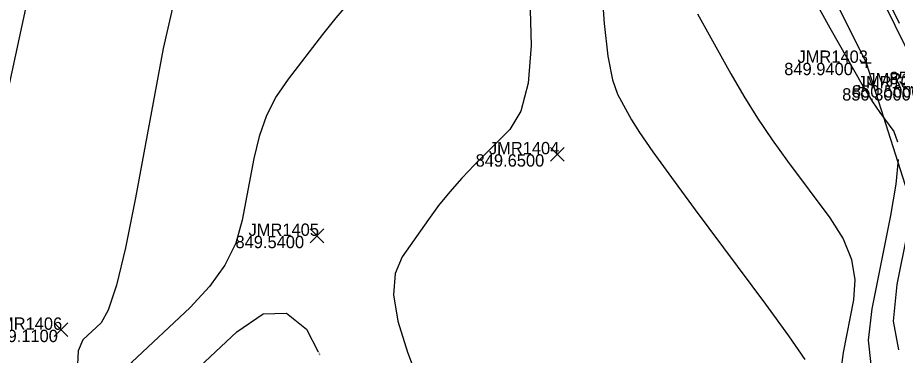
# Model space of a CAD drawing. Extents: x 1654928 to 1810050, y 486881 to 626330.
# Drawn here: x 1801294.2 to 1801380, y 489843.7 to 489876.6 of the extents above; entities that cross this region are included whole.
import ezdxf

# ---------------------------------------------------------------- set-up
doc = ezdxf.new("R2010")
doc.units = 0
for name, color, linetype in [('DT_X_Contour_Major', 7, 'Continuous'), ('DT_X_Contour_Minor', 7, 'Continuous'), ('RD_X_Fence', 7, 'Continuous'), ('SV_X_Occupation_Line', 7, 'Continuous'), ('SV_X_Random_Point', 7, 'Continuous'), ('SV_X_Shot_Marker', 7, 'Continuous'), ('SV_X_Text_Elevation', 7, 'Continuous'), ('SV_X_Text_Name', 7, 'Continuous')]:
    doc.layers.add(name, color=color, linetype=linetype)

msp = doc.modelspace()

# ---------------------------------------------------------------- linework, layer by layer
at = {"layer": 'DT_X_Contour_Major'}
for points in [[(1801292.361, 489865.603), (1801296.572, 489884.906)], [(1801360.479, 489876.984), (1801363.724, 489871.142), (1801364.981, 489868.967), (1801366.321, 489866.823), (1801367.743, 489864.709), (1801369.247, 489862.626), (1801373.367, 489857.111), (1801374.671, 489855.061), (1801375.493, 489853.047), (1801375.833, 489851.068), (1801375.691, 489849.125), (1801374.67, 489843.993), (1801374.464, 489842.265)]]:
    msp.add_lwpolyline(points, dxfattribs=at)
at = {"layer": 'DT_X_Contour_Minor'}
for points in [[(1801373.062, 489890.318), (1801380.158, 489876.06)], [(1801368.296, 489884.804), (1801373.394, 489875.625), (1801375.132, 489872.527), (1801376.52, 489870.118), (1801377.559, 489868.396), (1801378.248, 489867.362), (1801379.621, 489865.524), (1801379.987, 489864.495)], [(1801351.08, 489880.117), (1801351.381, 489876.029), (1801351.745, 489872.84), (1801352.172, 489870.552), (1801352.662, 489869.163), (1801354.053, 489866.66), (1801354.831, 489865.407), (1801356.123, 489863.528), (1801357.927, 489861.022), (1801360.246, 489857.889), (1801367.112, 489848.698), (1801369.354, 489845.626), (1801370.93, 489843.305)], [(1801309.522, 489878.719), (1801308.373, 489873.608), (1801305.658, 489859.045), (1801304.685, 489854.189), (1801303.801, 489850.543), (1801303.006, 489848.108), (1801302.3, 489846.882), (1801300.538, 489845.228), (1801300.066, 489844.148), (1801299.969, 489842.147), (1801300.248, 489839.224), (1801300.904, 489835.382), (1801303.154, 489823.906), (1801303.894, 489820.001), (1801304.427, 489816.89), (1801304.753, 489814.574), (1801304.872, 489813.053), (1801304.915, 489810.056), (1801304.987, 489809.626)], [(1801344.133, 489878.53), (1801344.238, 489873.895), (1801343.945, 489870.215), (1801343.254, 489867.489), (1801342.164, 489865.719), (1801338.726, 489862.272), (1801337.478, 489860.97), (1801336.312, 489859.648), (1801335.227, 489858.307), (1801334.224, 489856.947), (1801331.659, 489853.295), (1801330.971, 489851.688), (1801330.83, 489849.606), (1801331.237, 489847.049), (1801332.191, 489844.017), (1801335.465, 489835.3)], [(1801326.553, 489878.166), (1801325.199, 489876.58), (1801323.908, 489874.965), (1801320.55, 489870.624), (1801319.395, 489868.918), (1801318.451, 489867.057), (1801317.717, 489865.041), (1801317.193, 489862.87), (1801316.075, 489856.874), (1801315.442, 489854.656), (1801314.381, 489852.501), (1801312.893, 489850.409), (1801310.978, 489848.38), (1801305.3, 489843.051), (1801303.515, 489840.904), (1801302.419, 489838.461), (1801302.011, 489835.72), (1801302.291, 489832.683), (1801303.956, 489824.188), (1801304.505, 489821.235), (1801304.902, 489818.747), (1801305.148, 489816.724), (1801305.243, 489815.165), (1801305.258, 489814.065)], [(1801380.055, 489862.788), (1801379.825, 489860.401), (1801379.297, 489857.335), (1801377.49, 489848.254), (1801377.126, 489845.197), (1801377.39, 489842.834), (1801378.281, 489841.167), (1801379.799, 489840.194), (1801384.685, 489838.528)], [(1801382.02, 489861.108), (1801379.932, 489850.614), (1801379.576, 489847.059), (1801380.072, 489844.264)], [(1801306.975, 489810.002), (1801306.42, 489810.255), (1801306.018, 489810.873), (1801305.768, 489811.855), (1801305.67, 489813.202), (1801305.613, 489817.278), (1801305.543, 489818.874), (1801305.378, 489820.605), (1801305.116, 489822.47), (1801304.759, 489824.47), (1801303.678, 489829.985), (1801303.663, 489832.113), (1801304.428, 489834.361), (1801305.974, 489836.73), (1801308.3, 489839.219), (1801315.544, 489846.018), (1801318.11, 489847.747), (1801320.373, 489847.833), (1801322.335, 489846.278), (1801323.48, 489844.074)]]:
    msp.add_lwpolyline(points, dxfattribs=at)
at = {"layer": 'RD_X_Fence'}
msp.add_lwpolyline([(1801327.157, 489980.825), (1801341.337, 489952.815), (1801353.978, 489927.719), (1801368.649, 489898.399), (1801382.749, 489869.731), (1801399.284, 489836.538), (1801405.615, 489823.327), (1801393.757, 489823.044), (1801375.98, 489823.449), (1801361.092, 489823.97), (1801335.059, 489824.221), (1801306.244, 489824.992)], dxfattribs=at)
at = {"layer": 'SV_X_Occupation_Line'}
msp.add_lwpolyline([(1801323.637, 489975.339), (1801342.746, 489938.404), (1801356.309, 489913.548), (1801376.911, 489872.203), (1801387.619, 489838.687), (1801379.855, 489831.976), (1801347.713, 489831.536), (1801304.639, 489830.454)], dxfattribs=at)
at = {"layer": 'SV_X_Random_Point'}
for p, q in [((1801346.133, 489862.63), (1801347.467, 489863.965)), ((1801346.133, 489863.965), (1801347.467, 489862.63)), ((1801322.7, 489854.686), (1801324.033, 489856.021)), ((1801322.7, 489856.021), (1801324.033, 489854.686)), ((1801297.729, 489845.541), (1801299.062, 489846.876)), ((1801297.729, 489846.876), (1801299.062, 489845.541))]:
    msp.add_line(p, q, dxfattribs=at)
at = {"layer": 'SV_X_Shot_Marker'}
for p, q in [((1801376.911, 489872.703), (1801376.911, 489871.703)), ((1801376.411, 489872.203), (1801377.411, 489872.203)), ((1801376.911, 489872.203), (1801376.911, 489872.203))]:
    msp.add_line(p, q, dxfattribs=at)

# ---------------------------------------------------------------- texts
at = {"layer": 'DT_X_Contour_Minor'}
msp.add_text('850', height=0.14, rotation=117.43981, dxfattribs=at).set_placement((1801323.715, 489843.773))
at = {"layer": 'SV_X_Text_Elevation'}
for s, p in [('849.9400', (1801368.936, 489871.003)), ('850.5700', (1801379.198, 489870.13)), ('850.5000', (1801375.543, 489868.823)), ('850.3000', (1801374.586, 489868.531)), ('849.6500', (1801338.835, 489862.097)), ('849.5400', (1801315.411, 489854.154)), ('849.1100', (1801291.395, 489845.008))]:
    msp.add_text(s, height=1.2, dxfattribs=at).set_placement(p)
at = {"layer": 'SV_X_Text_Name'}
for s, p in [('JMR1403', (1801370.231, 489872.203)), ('JMR1023', (1801376.098, 489869.731)), ('JMR1022', (1801377.045, 489870.023)), ('JMR1404', (1801340.13, 489863.297)), ('JMR1405', (1801316.687, 489855.354)), ('JMR1406', (1801291.641, 489846.208))]:
    msp.add_text(s, height=1.2, dxfattribs=at).set_placement(p)

doc.saveas('drawing.dxf')
